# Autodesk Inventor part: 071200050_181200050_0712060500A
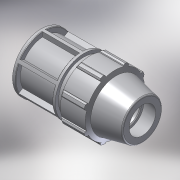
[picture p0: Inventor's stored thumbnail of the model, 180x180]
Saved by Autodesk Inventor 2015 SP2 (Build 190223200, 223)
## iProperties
Created: 2017-02
Part Number: 071200050_181200050_0712060500A
Material: PVC-Piping
Description: PLASSON END PLUG 50
Document SubType Name: Modeling
Designer: KIM
Mass: 92.6774 g
Surface Area: 199.44 cm^2
Volume: 66.1981 cm^3
Density: 1.4 g/cm^3
Appearance: Smooth - White
Author: Кирилл
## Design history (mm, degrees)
derived "07120.ipt"
feature "Solid1::07120.ipt"
tag "TaggingFeature1"
body "Solid1"
other parameters: "d4" = 17.28571, "d5" = 30.25, "d7" = 96, "d8" = 72, "d9" = 17.28571, "d11" = 3.45714, "d12" = 76.8, "d13" = 120 deg, "d14" = 75, "d15" = 12 deg, "d16" = 86.4, "d18" = 2.5, "d19" = 35 deg, "d20" = 17.5 deg, "d21" = 89.28, "d23" = 0, "d25" = 360 deg, "d27" = 1.92, "d34" = 4.8, "d36" = 0, "d42" = 30.25, "d43" = 2.88, "d46" = 1.5, "d53" = 1, "d55" = 360 deg, "d59" = 42.35, "d64" = 121, "d66" = 9.6, "d67" = 4.8, "d68" = 114, "E_" = 96, "H_" = 121, "l_" = 114
